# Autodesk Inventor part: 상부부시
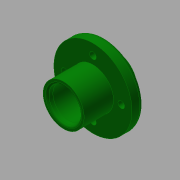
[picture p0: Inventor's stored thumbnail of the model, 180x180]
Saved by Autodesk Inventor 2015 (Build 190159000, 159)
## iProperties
Created: 2015-12
Part Number: 상부부시
Material: 강철, 연강
Document SubType Name: Modeling
Designer: mduedu
Density: 7.86 g/cm^3
Appearance: 진녹색
Author: mduedu
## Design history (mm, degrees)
sketch "스케치1"
  geometry: C1 r 10.5 at (0, 0); C2 r 8 at (0, 0); 1 further point
  constraints: 2 centre point, 2 coincident
  dimensions: "d1" = 21 diameter of C1; "d3" = 16 diameter of C2
extrude "돌출1" new body sketch "스케치1" distance "d4" = 12; taper "d6" = 0 deg; dims "d5" = 15, "d7" = 0
sketch "스케치2"
  geometry: C1 r 20 at (0, 0); C2 r 10.5 at (0, 0) reference; 1 further point
  constraints: 1 centre point, 1 coincident
  dimensions: "d8" = 40 diameter of C1
extrude "돌출2" join sketch "스케치2" distance "d10" = 6; taper "d11" = 0 deg
chamfer "모따기1" distance "d12" = 2.5; stored, may be unused: second distance "d13" = 2, angle "d14" = 10 deg
chamfer "모따기2" distance "d15" = 2.5; stored, may be unused: second distance "d16" = 2, angle "d17" = 10 deg
fillet "모깎기1" dims "d18" = 1
fillet "모깎기2" dims "d19" = 2
sketch "스케치3" dims "d20" = 29
  geometry: 6 further points
  constraints: 2 vertical alignment, 1 coincident, 7 other
  dimensions: "d24" = 360 deg dimension on point (0, 0) point (0, 14.5) (derived)
sketch "스케치4"
  geometry: 4 further points
hole "구멍1" sketch "스케치4" at (-14.5, 0), (0, -14.5), (14.5, 0), (0, 14.5) diameter "d26" = 3.4; stored, may be unused: countersink angle "d30" = 90 deg, drill point angle "d32" = 0 deg; dims "d27" = 6, "d28" = 6.5, "d29" = 3.4, "d31" = 8
fillet "모깎기3" dims "d33" = 1
node "솔리드1"
